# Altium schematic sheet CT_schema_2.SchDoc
size 276 x 169 mm
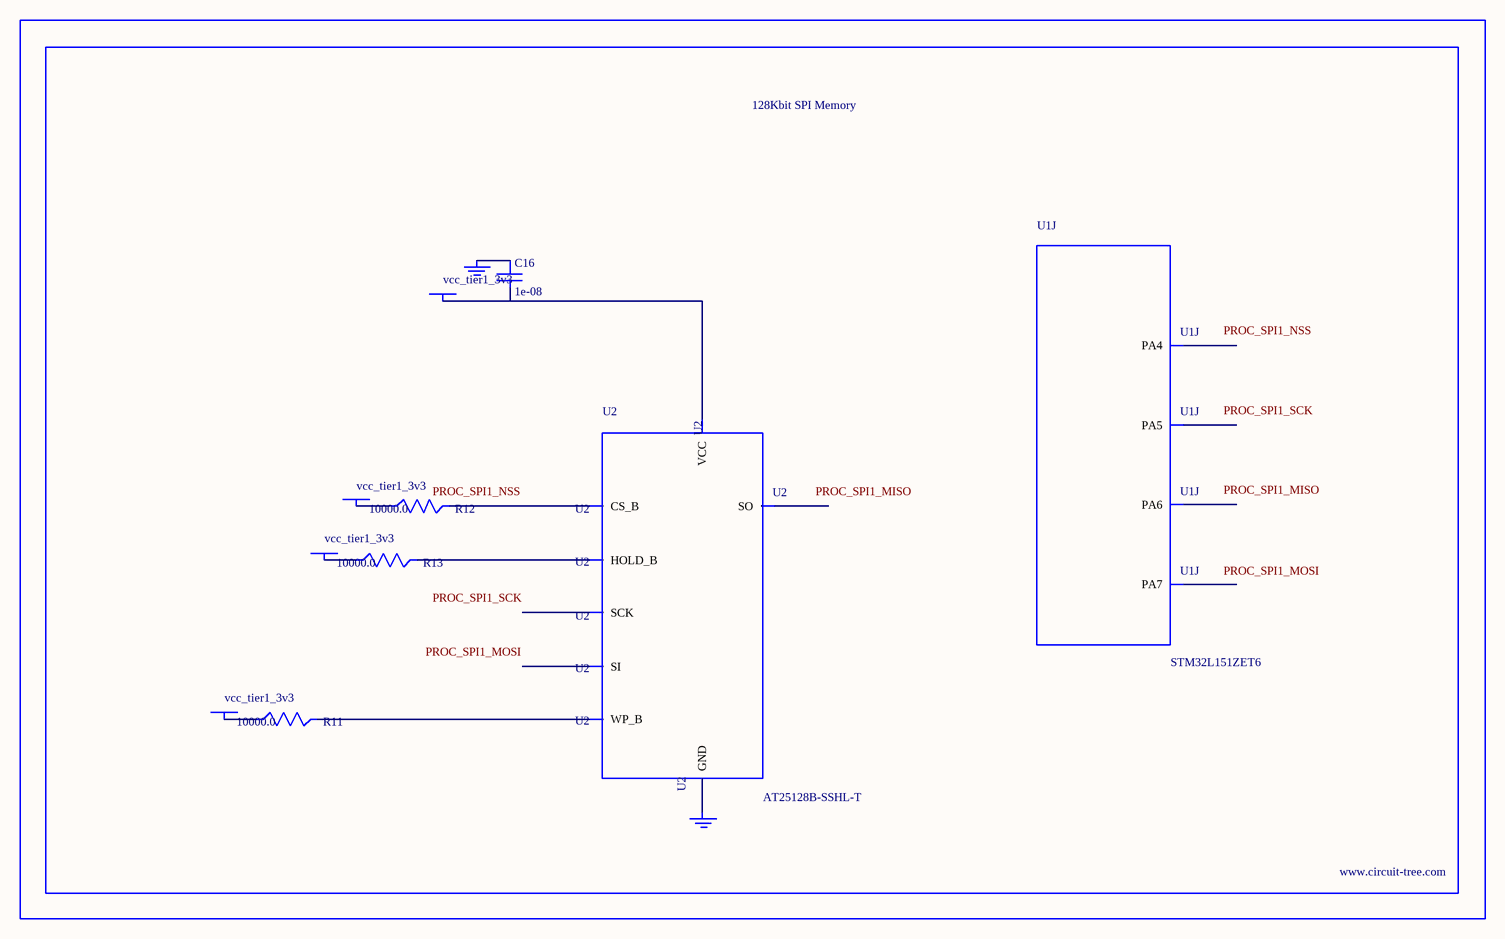
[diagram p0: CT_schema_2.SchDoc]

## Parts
BORDER1  (no value)
C16  1e-08  [C0402]
GND_INSTANCE_1_0  (no value)
GND_INSTANCE_1_1  (no value)
POWER_INSTANCE_1_0  vcc_tier1_3v3
POWER_INSTANCE_1_1  vcc_tier1_3v3
POWER_INSTANCE_1_2  vcc_tier1_3v3
POWER_INSTANCE_1_3  vcc_tier1_3v3
R11  10000.0  [R0603]
R12  10000.0  [R0603]
R13  10000.0  [R0603]
U1  STM32L151ZET6  [LQFP144]  (part J of 14)
U2  AT25128B-SSHL-T  [SOIC-8]

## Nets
NetC16_1: C16.1 GND_INSTANCE_1_0.0(GND)
NetC16_2: C16.2 POWER_INSTANCE_1_3.0(PWR) U2.8(VCC)
NetGND_INSTANCE_1_1_0: GND_INSTANCE_1_1.0(GND) U2.4(GND)
NetPOWER_INSTANCE_1_0_0: POWER_INSTANCE_1_0.0(PWR) R12.1
NetPOWER_INSTANCE_1_1_0: POWER_INSTANCE_1_1.0(PWR) R11.1
NetPOWER_INSTANCE_1_2_0: POWER_INSTANCE_1_2.0(PWR) R13.1
NetR11_2: R11.2 U2.3(WP_B)
NetR12_2: R12.2 U2.1(CS_B)
NetR13_2: R13.2 U2.7(HOLD_B)

Not connected (* = marked no-connect by the designer): U1 40(PA4) 41(PA5) 42(PA6) 43(PA7); U2 2(SO) 5(SI) 6(SCK)

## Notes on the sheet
- Labels drawn without touching a wire or pin: PROC_SPI1_MISO, PROC_SPI1_MOSI, PROC_SPI1_NSS, PROC_SPI1_SCK

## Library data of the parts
BORDER1 = BORDER_PAGE1
C16 = C0402C103K3RAC
GND_INSTANCE_1_0 GND_INSTANCE_1_1 = GND
POWER_INSTANCE_1_0-POWER_INSTANCE_1_3 = PWR
R11-R13 = RC0603JR-0710KL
